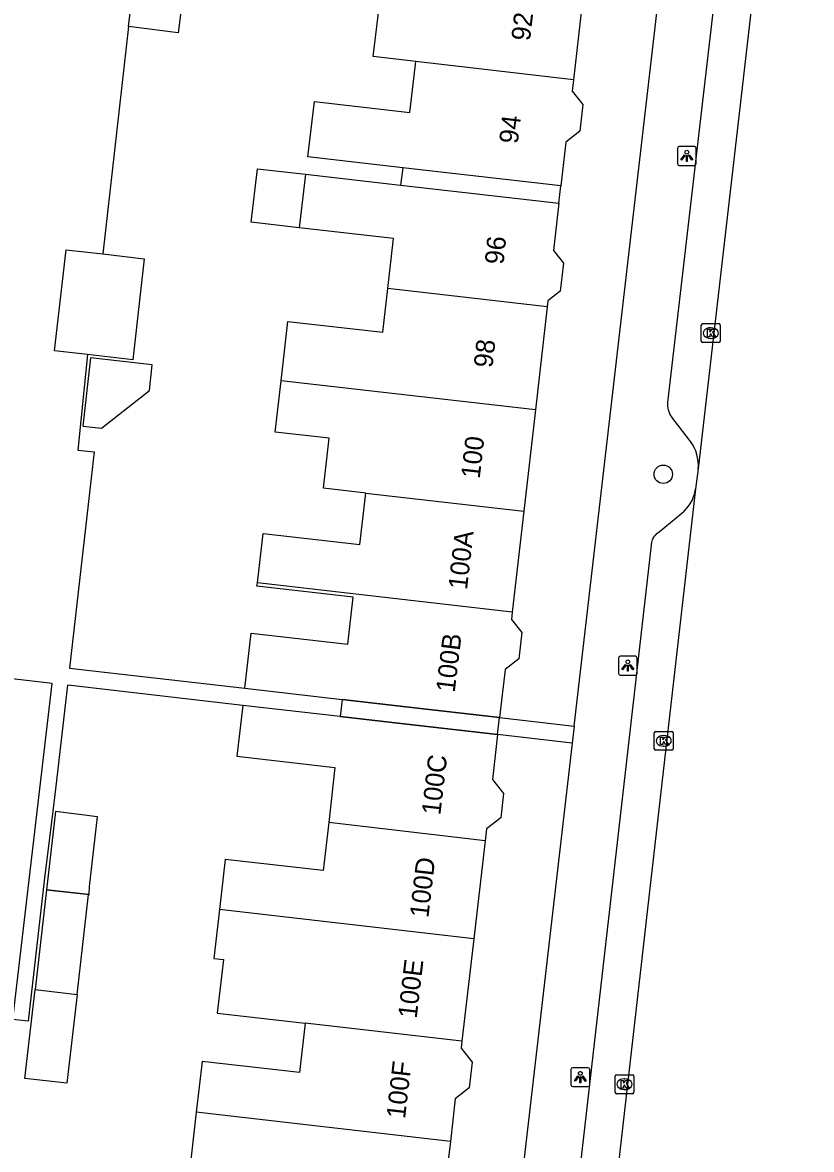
# Model space of a CAD drawing. Extents: x 161696 to 162377, y 380761 to 381673.
# Drawn here: x 162273.5 to 162315.3, y 381257 to 381316.7 of the extents above; entities that cross this region are included whole.
import ezdxf

# ---------------------------------------------------------------- set-up
doc = ezdxf.new("R2010")
doc.units = 0
for name, color, linetype in [('IMGEO_Boom', 7, 'Continuous'), ('IMGEO_Kolk', 7, 'Continuous'), ('IMGEO_Lichtpunt', 7, 'Continuous'), ('IMGEO_Pand', 7, 'Continuous'), ('IMGEO_Pand_nummerreeks', 7, 'Continuous'), ('IMGEO_Pand_overbouw', 7, 'Continuous'), ('IMGEO_Rijbaan_lokaal_gesloten', 7, 'Continuous'), ('IMGEO_Voetpad_open', 7, 'Continuous')]:
    doc.layers.add(name, color=color, linetype=linetype)

msp = doc.modelspace()

# ---------------------------------------------------------------- linework, layer by layer
at = {"layer": 'IMGEO_Boom'}
msp.add_circle((162307.416, 381292.801), 0.489, dxfattribs=at)
at = {"layer": 'IMGEO_Kolk'}
for p, q in [((162309.435, 381299.856), (162309.435, 381300.708)), ((162309.51, 381300.782), (162310.362, 381300.782)), ((162309.923, 381300.562), (162309.948, 381300.562)), ((162310.436, 381300.708), (162310.436, 381299.856)), ((162310.362, 381299.782), (162309.51, 381299.782)), ((162309.946, 381300.002), (162309.921, 381300.002)), ((162306.943, 381278.246), (162306.943, 381279.098)), ((162307.018, 381279.172), (162307.87, 381279.172)), ((162307.431, 381278.952), (162307.456, 381278.952)), ((162307.944, 381279.098), (162307.944, 381278.246)), ((162307.454, 381278.392), (162307.429, 381278.392)), ((162307.87, 381278.172), (162307.018, 381278.172)), ((162304.935, 381260.971), (162305.787, 381260.971)), ((162304.86, 381260.045), (162304.86, 381260.897)), ((162305.348, 381260.751), (162305.373, 381260.751)), ((162305.861, 381260.897), (162305.861, 381260.045)), ((162305.787, 381259.971), (162304.935, 381259.971)), ((162305.371, 381260.191), (162305.346, 381260.191))]:
    msp.add_line(p, q, dxfattribs=at)
for points in [[(162309.435, 381299.856), (162309.435, 381300.708)], [(162309.51, 381300.782), (162310.362, 381300.782)], [(162309.756, 381300.482), (162309.879, 381300.482), (162309.879, 381300.331), (162310.009, 381300.482), (162310.173, 381300.482), (162310.027, 381300.331), (162310.18, 381300.082), (162310.028, 381300.082), (162309.943, 381300.246), (162309.879, 381300.179), (162309.879, 381300.082), (162309.756, 381300.082), (162309.756, 381300.482)], [(162310.436, 381300.708), (162310.436, 381299.856)], [(162310.362, 381299.782), (162309.51, 381299.782)], [(162306.943, 381278.246), (162306.943, 381279.098)], [(162307.018, 381279.172), (162307.87, 381279.172)], [(162307.264, 381278.872), (162307.387, 381278.872), (162307.387, 381278.721), (162307.517, 381278.872), (162307.681, 381278.872), (162307.535, 381278.721), (162307.688, 381278.472), (162307.536, 381278.472), (162307.451, 381278.636), (162307.387, 381278.569), (162307.387, 381278.472), (162307.264, 381278.472), (162307.264, 381278.872)], [(162307.944, 381279.098), (162307.944, 381278.246)], [(162307.87, 381278.172), (162307.018, 381278.172)], [(162304.935, 381260.971), (162305.787, 381260.971)], [(162304.86, 381260.045), (162304.86, 381260.897)], [(162305.181, 381260.671), (162305.304, 381260.671), (162305.304, 381260.52), (162305.434, 381260.671), (162305.598, 381260.671), (162305.452, 381260.52), (162305.605, 381260.271), (162305.453, 381260.271), (162305.368, 381260.435), (162305.304, 381260.368), (162305.304, 381260.271), (162305.181, 381260.271), (162305.181, 381260.671)], [(162305.861, 381260.897), (162305.861, 381260.045)], [(162305.787, 381259.971), (162304.935, 381259.971)]]:
    msp.add_lwpolyline(points, dxfattribs=at)
for centre, start, end in [((162309.512, 381300.706), 91.55205, 178.44795), ((162309.512, 381300.706), 91.55205, 178.44795), ((162310.36, 381300.706), 1.55205, 88.44795), ((162310.36, 381300.706), 1.55205, 88.44795), ((162309.512, 381299.858), 181.55205, 268.44795), ((162309.512, 381299.858), 181.55205, 268.44795), ((162310.36, 381299.858), 271.55205, 358.44795), ((162310.36, 381299.858), 271.55205, 358.44795), ((162307.02, 381279.096), 91.55205, 178.44795), ((162307.02, 381279.096), 91.55205, 178.44795), ((162307.868, 381279.096), 1.55205, 88.44795), ((162307.868, 381279.096), 1.55205, 88.44795), ((162307.02, 381278.248), 181.55205, 268.44795), ((162307.02, 381278.248), 181.55205, 268.44795), ((162307.868, 381278.248), 271.55205, 358.44795), ((162307.868, 381278.248), 271.55205, 358.44795), ((162304.937, 381260.895), 91.55205, 178.44795), ((162304.937, 381260.895), 91.55205, 178.44795), ((162305.785, 381260.895), 1.55205, 88.44795), ((162305.785, 381260.895), 1.55205, 88.44795), ((162304.937, 381260.047), 181.55205, 268.44795), ((162304.937, 381260.047), 181.55205, 268.44795), ((162305.785, 381260.047), 271.55205, 358.44795), ((162305.785, 381260.047), 271.55205, 358.44795)]:
    msp.add_arc(centre, 0.0765, start, end, dxfattribs=at)
for centre, major_axis, ratio, start_param, end_param in [((162309.922, 381300.282), (-0.387, 0.002), 0.722429, 4.712389, 7.853982), ((162309.947, 381300.282), (-0.39, 0.002), 0.717154, 1.570796, 4.712389), ((162307.43, 381278.672), (-0.387, 0.002), 0.722429, 4.712389, 7.853982), ((162307.455, 381278.672), (-0.39, 0.002), 0.717154, 1.570796, 4.712389), ((162305.347, 381260.471), (-0.387, 0.002), 0.722429, 4.712389, 7.853982), ((162305.372, 381260.471), (-0.39, 0.002), 0.717154, 1.570796, 4.712389)]:
    msp.add_ellipse(centre, major_axis=major_axis, ratio=ratio, start_param=start_param, end_param=end_param, dxfattribs=at)
at = {"layer": 'IMGEO_Lichtpunt'}
for p, q in [((162308.167, 381310.074), (162308.167, 381309.267)), ((162308.167, 381310.074), (162308.167, 381309.267)), ((162309.069, 381310.169), (162308.261, 381310.169)), ((162309.069, 381310.169), (162308.261, 381310.169)), ((162309.163, 381309.267), (162309.163, 381310.074)), ((162309.163, 381309.267), (162309.163, 381310.074)), ((162308.261, 381309.173), (162309.069, 381309.173)), ((162308.261, 381309.173), (162309.069, 381309.173)), ((162305.038, 381283.061), (162305.038, 381282.254)), ((162305.038, 381283.061), (162305.038, 381282.254)), ((162305.94, 381283.156), (162305.132, 381283.156)), ((162305.94, 381283.156), (162305.132, 381283.156)), ((162306.034, 381282.254), (162306.034, 381283.061)), ((162306.034, 381282.254), (162306.034, 381283.061)), ((162305.132, 381282.16), (162305.94, 381282.16)), ((162305.132, 381282.16), (162305.94, 381282.16)), ((162302.522, 381261.251), (162302.522, 381260.444)), ((162302.522, 381261.251), (162302.522, 381260.444)), ((162303.424, 381261.346), (162302.616, 381261.346)), ((162303.424, 381261.346), (162302.616, 381261.346)), ((162303.518, 381260.444), (162303.518, 381261.251)), ((162303.518, 381260.444), (162303.518, 381261.251)), ((162302.616, 381260.35), (162303.424, 381260.35)), ((162302.616, 381260.35), (162303.424, 381260.35))]:
    msp.add_line(p, q, dxfattribs=at)
for points in [[(162308.541, 381309.738), (162308.58, 381309.71), (162308.392, 381309.448), (162308.354, 381309.475), (162308.541, 381309.738)], [(162308.643, 381309.69), (162308.69, 381309.69), (162308.69, 381309.368), (162308.643, 381309.368), (162308.643, 381309.69)], [(162308.753, 381309.71), (162308.791, 381309.737), (162308.978, 381309.475), (162308.939, 381309.447), (162308.753, 381309.71)], [(162305.412, 381282.725), (162305.451, 381282.697), (162305.263, 381282.435), (162305.225, 381282.462), (162305.412, 381282.725)], [(162305.514, 381282.677), (162305.561, 381282.677), (162305.561, 381282.355), (162305.514, 381282.355), (162305.514, 381282.677)], [(162305.624, 381282.697), (162305.662, 381282.724), (162305.849, 381282.462), (162305.81, 381282.434), (162305.624, 381282.697)], [(162302.896, 381260.915), (162302.935, 381260.887), (162302.747, 381260.625), (162302.709, 381260.652), (162302.896, 381260.915)], [(162303.108, 381260.887), (162303.146, 381260.914), (162303.333, 381260.652), (162303.294, 381260.624), (162303.108, 381260.887)], [(162302.998, 381260.867), (162303.045, 381260.867), (162303.045, 381260.545), (162302.998, 381260.545), (162302.998, 381260.867)]]:
    msp.add_lwpolyline(points, dxfattribs=at)
for centre in [(162308.666, 381309.872), (162305.537, 381282.859), (162303.021, 381261.049)]:
    msp.add_circle(centre, 0.0994, dxfattribs=at)
for centre, start, end in [((162308.261, 381310.074), 90, 180), ((162308.261, 381310.074), 90, 180), ((162309.069, 381310.074), 0, 90), ((162309.069, 381310.074), 0, 90), ((162308.261, 381309.267), 180, 270), ((162308.261, 381309.267), 180, 270), ((162309.069, 381309.267), 270, 0), ((162309.069, 381309.267), 270, 360), ((162305.132, 381283.061), 90, 180), ((162305.132, 381283.061), 90, 180), ((162305.94, 381283.061), 0, 90), ((162305.94, 381283.061), 0, 90), ((162305.132, 381282.254), 180, 270), ((162305.132, 381282.254), 180, 270), ((162305.94, 381282.254), 270, 0), ((162305.94, 381282.254), 270, 360), ((162302.616, 381261.251), 90, 180), ((162302.616, 381261.251), 90, 180), ((162303.424, 381261.251), 0, 90), ((162303.424, 381261.251), 0, 90), ((162302.616, 381260.444), 180, 270), ((162302.616, 381260.444), 180, 270), ((162303.424, 381260.444), 270, 0), ((162303.424, 381260.444), 270, 360)]:
    msp.add_arc(centre, 0.0946, start, end, dxfattribs=at)
at = {"layer": 'IMGEO_Pand'}
for points in [[(162294.299, 381314.678), (162292.046, 381314.943), (162292.352, 381317.544), (162289.592, 381317.859), (162289.92, 381320.726)], [(162279.565, 381320.612), (162282.212, 381320.286), (162281.707, 381316.197), (162279.061, 381316.524)], [(162279.061, 381316.524), (162279.565, 381320.612)], [(162303.274, 381319.157), (162302.65, 381313.696)], [(162302.65, 381313.696), (162302.582, 381313.103), (162303.148, 381312.391), (162302.987, 381310.988), (162302.246, 381310.399), (162301.98, 381308.081), (162297.013, 381308.648), (162293.605, 381309.039), (162288.576, 381309.617), (162288.93, 381312.555), (162293.99, 381311.976), (162294.299, 381314.678)], [(162302.65, 381313.696), (162294.299, 381314.678)], [(162288.11, 381305.868), (162285.578, 381306.158), (162285.915, 381308.993), (162288.447, 381308.704)], [(162288.447, 381308.704), (162288.11, 381305.868)], [(162288.447, 381308.704), (162293.486, 381308.129), (162296.91, 381307.739), (162301.877, 381307.17), (162301.59, 381304.663), (162302.122, 381303.993), (162301.953, 381302.511), (162301.303, 381301.994), (162301.266, 381301.672)], [(162292.811, 381302.642), (162293.114, 381305.295), (162288.11, 381305.868)], [(162276.903, 381299.145), (162275.153, 381299.346), (162275.767, 381304.698), (162277.711, 381304.475)], [(162277.711, 381304.475), (162279.906, 381304.223), (162279.292, 381298.871), (162276.903, 381299.145)], [(162287.163, 381297.76), (162287.522, 381300.898), (162292.546, 381300.324), (162292.811, 381302.642)], [(162301.266, 381301.672), (162292.811, 381302.642)], [(162301.266, 381301.672), (162300.642, 381296.215)], [(162277.045, 381298.978), (162276.656, 381295.351), (162277.643, 381295.245), (162280.181, 381297.247), (162280.326, 381298.601), (162277.045, 381298.978)], [(162291.646, 381291.802), (162289.411, 381292.059), (162289.713, 381294.705), (162286.851, 381295.032), (162287.163, 381297.76)], [(162300.642, 381296.215), (162287.163, 381297.76)], [(162300.642, 381296.215), (162300.027, 381290.84)], [(162285.901, 381287.05), (162286.2, 381289.663), (162291.334, 381289.075), (162291.646, 381291.802)], [(162291.646, 381291.802), (162300.027, 381290.84)], [(162300.027, 381290.84), (162299.416, 381285.499)], [(162285.23, 381281.459), (162285.564, 381284.38), (162290.693, 381283.793), (162290.978, 381286.283), (162285.88, 381286.866), (162285.901, 381287.05)], [(162299.416, 381285.499), (162285.901, 381287.05)], [(162299.416, 381285.499), (162299.37, 381285.095), (162299.915, 381284.409), (162299.756, 381283.025), (162299.029, 381282.447), (162298.738, 381279.911)], [(162272.937, 381263.902), (162275.022, 381281.707), (162264.127, 381282.983)], [(162285.23, 381281.459), (162290.389, 381280.868), (162293.771, 381280.48), (162298.738, 381279.911)], [(162285.126, 381280.551), (162284.817, 381277.853), (162290.015, 381277.258), (162289.681, 381274.335)], [(162298.636, 381279.004), (162293.669, 381279.573), (162290.295, 381279.959), (162285.126, 381280.551)], [(162298.636, 381279.004), (162298.359, 381276.629), (162298.951, 381275.883), (162298.801, 381274.593), (162298.051, 381273.999), (162297.979, 381273.38)], [(162274.726, 381270.777), (162276.986, 381270.529), (162277.005, 381270.952), (162277.43, 381274.652), (162275.204, 381274.93), (162274.778, 381271.231), (162274.726, 381270.777)], [(162289.681, 381274.335), (162289.39, 381271.796), (162284.196, 381272.39), (162283.891, 381269.724)], [(162297.979, 381273.38), (162289.681, 381274.335)], [(162297.979, 381273.38), (162297.374, 381268.174)], [(162274.726, 381270.777), (162274.117, 381265.484)], [(162276.346, 381265.228), (162276.955, 381270.521), (162274.726, 381270.777)], [(162283.891, 381269.724), (162283.596, 381267.14), (162284.097, 381267.083), (162283.772, 381264.241), (162288.427, 381263.709)], [(162297.374, 381268.174), (162283.891, 381269.724)], [(162297.374, 381268.174), (162296.744, 381262.752)], [(162276.346, 381265.228), (162275.804, 381260.527), (162273.576, 381260.783), (162274.117, 381265.484)], [(162274.117, 381265.484), (162276.346, 381265.228)], [(162288.427, 381263.709), (162288.128, 381261.093), (162282.967, 381261.684), (162282.659, 381258.995)], [(162296.744, 381262.752), (162288.427, 381263.709)], [(162296.744, 381262.752), (162296.7, 381262.374), (162297.28, 381261.642), (162297.121, 381260.273), (162296.391, 381259.695), (162296.13, 381257.444)], [(162282.659, 381258.995), (162282.37, 381256.465), (162287.509, 381255.877), (162287.196, 381253.284)], [(162296.13, 381257.444), (162282.659, 381258.995)], [(162296.13, 381257.444), (162295.864, 381255.154), (162296.445, 381254.42), (162296.282, 381253.018), (162295.564, 381252.449), (162295.55, 381252.324)]]:
    msp.add_lwpolyline(points, dxfattribs=at)
at = {"layer": 'IMGEO_Pand_overbouw'}
for points in [[(162293.486, 381308.129), (162296.91, 381307.739), (162301.877, 381307.17), (162301.98, 381308.081), (162297.013, 381308.648), (162293.605, 381309.039)], [(162298.636, 381279.004), (162298.738, 381279.911), (162293.771, 381280.48), (162290.389, 381280.868), (162290.295, 381279.959), (162293.669, 381279.573)]]:
    msp.add_lwpolyline(points, close=True, dxfattribs=at)
at = {"layer": 'IMGEO_Rijbaan_lokaal_gesloten'}
for points in [[(162315.274, 381345.174), (162309.272, 381293.094)], [(162309.272, 381293.094), (162309.123, 381292.03)], [(162309.123, 381292.03), (162307.201, 381275.19), (162303.256, 381240.642)]]:
    msp.add_lwpolyline(points, dxfattribs=at)
at = {"layer": 'IMGEO_Voetpad_open'}
for points in [[(162302.701, 381279.452), (162309.892, 381341.504), (162312.515, 381364.604)], [(162309.272, 381293.094), (162309.279, 381293.286), (162309.269, 381293.478), (162309.241, 381293.668), (162309.197, 381293.855), (162309.136, 381294.037), (162309.059, 381294.213), (162308.966, 381294.382), (162308.859, 381294.541), (162308.809, 381294.606), (162307.873, 381295.827), (162307.867, 381295.836), (162307.812, 381295.921), (162307.764, 381296.011), (162307.725, 381296.105), (162307.695, 381296.202), (162307.673, 381296.302), (162307.66, 381296.403), (162307.657, 381296.504), (162307.662, 381296.606), (162312.954, 381342.236)], [(162279.061, 381316.524), (162277.711, 381304.475)], [(162276.903, 381299.145), (162276.376, 381294.08), (162277.249, 381293.98), (162275.932, 381282.517), (162285.23, 381281.459)], [(162301.637, 381243.935), (162306.786, 381289.038), (162306.791, 381289.103), (162306.803, 381289.181), (162306.822, 381289.258), (162306.848, 381289.332), (162306.881, 381289.404), (162306.92, 381289.472), (162306.964, 381289.537), (162307.015, 381289.598), (162307.07, 381289.653), (162307.131, 381289.704), (162307.195, 381289.749), (162308.395, 381290.735), (162308.528, 381290.85), (162308.649, 381290.977), (162308.759, 381291.114), (162308.857, 381291.26), (162308.941, 381291.415), (162309.01, 381291.576), (162309.065, 381291.743), (162309.105, 381291.914), (162309.123, 381292.03)], [(162285.126, 381280.551), (162276.006, 381281.597), (162275.829, 381281.619), (162275.223, 381276.269), (162275.063, 381274.948), (162274.601, 381271.253), (162273.75, 381263.809), (162272.937, 381263.902)], [(162298.738, 381279.911), (162302.701, 381279.452)], [(162302.701, 381279.452), (162302.596, 381278.545)], [(162302.596, 381278.545), (162298.636, 381279.004)], [(162302.596, 381278.545), (162296.033, 381221.909)]]:
    msp.add_lwpolyline(points, dxfattribs=at)

# ---------------------------------------------------------------- texts
at = {"layer": 'IMGEO_Pand_nummerreeks'}
for s, rotation, p in [('92', 83.26423, (162300.347, 381315.737)), ('94', 83.26423, (162299.702, 381310.284)), ('96', 84.39383, (162298.947, 381303.888)), ('98', 83.47456, (162298.357, 381298.412)), ('100', 83.47422, (162297.684, 381292.538)), ('100A', 83.47456, (162297.011, 381286.65)), ('100B', 83.07989, (162296.357, 381281.204)), ('100C', 83.33686, (162295.596, 381274.704)), ('100D', 83.37127, (162294.964, 381269.263)), ('100E', 83.37234, (162294.344, 381263.927)), ('100F', 83.40167, (162293.727, 381258.605))]:
    msp.add_text(s, height=1, rotation=rotation, dxfattribs=at).set_placement(p)

doc.saveas('drawing.dxf')
